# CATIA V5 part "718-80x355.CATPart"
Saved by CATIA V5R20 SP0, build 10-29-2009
Part number: 718-80x355
Definition: NONE
Nomenclature: 718-80x355
Source: Unknown
Description: 718-80x355
Bounding box of the stored display mesh (mm): x 0 to 415, y -47.5 to 47.5, z -47.5 to 47.5
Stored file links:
  C:\Users\Utente\Desktop\IO LAVORO\3D X SITO CF\X SITO\718\718-80x355.CATPart

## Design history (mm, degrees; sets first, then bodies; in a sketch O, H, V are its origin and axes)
Body1 "718-80x355" (main body)
  Solid1: solid without history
